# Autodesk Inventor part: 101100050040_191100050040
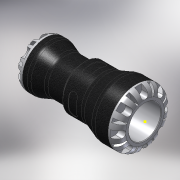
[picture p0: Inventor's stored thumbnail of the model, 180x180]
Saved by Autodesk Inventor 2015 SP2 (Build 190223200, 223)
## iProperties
Created: 2016-12
Part Number: 101100050040_191100050040
Material: PVC-Piping
Description: PLASSON REDUCING COUPLING 50X40 SERIES 1
Document SubType Name: Modeling
Designer: KIM
Mass: 411.954 g
Surface Area: 655.477 cm^2
Volume: 294.253 cm^3
Density: 1.4 g/cm^3
Appearance: Black Cast
Author: KIM
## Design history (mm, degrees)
derived "1011.ipt"
feature "Solid1::1011.ipt"
tag "TaggingFeature1"
body "Solid1"
other parameters: "d0" = 165, "d2" = 32.34, "d4" = 85, "d6" = 77, "d7" = 4.16667, "d8" = 58, "d11" = 22.26, "d12" = 53, "d13" = 3.33333, "d14" = 68, "d15" = 46.4, "d16" = 20 deg, "d17" = 20 deg, "d18" = 130 deg, "d26" = 0, "d28" = 360 deg, "d30" = 8 deg, "d31" = 1, "d32" = 8 deg, "d33" = 1, "d35" = 0, "d37" = 360 deg, "d39" = 3.2, "d42" = 3.2, "d43" = 0, "d45" = 360 deg, "d47" = 0.8, "d48" = 8 deg, "d49" = 8 deg, "d50" = 0.8, "d52" = 0, "d54" = 360 deg, "d56" = 11.6, "d57" = 17, "d58" = 0.5, "d60" = 10.2, "d61" = 12.5, "d62" = 16.2, "d63" = 0, "d66" = 0, "d68" = 360 deg, "d75" = 13.25673, "d77" = 66.3, "d78" = 0.85, "E_" = 85, "H_" = 165, "l_" = 77, "E1" = 58, "l1" = 53, "Plasson" = 1, "d20" = 4, "d21" = 12.5, "d23" = 85, "d40" = 58, "d59" = 26.51345
